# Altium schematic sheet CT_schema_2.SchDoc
size 276 x 169 mm
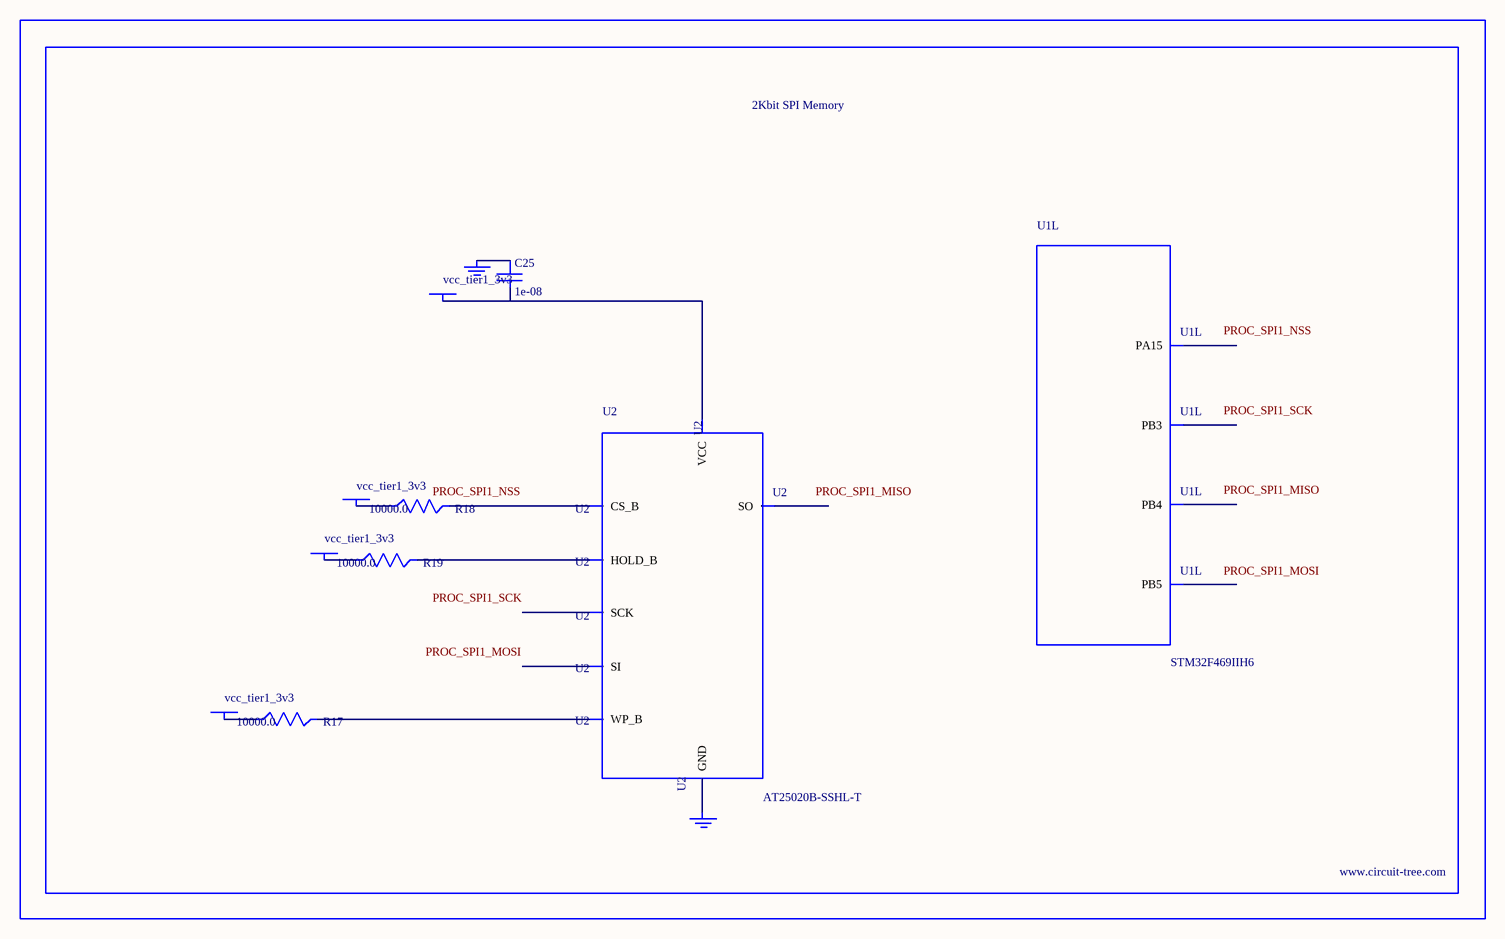
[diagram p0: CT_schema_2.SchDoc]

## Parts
BORDER1  (no value)
C25  1e-08  [C0402]
GND_INSTANCE_1_0  (no value)
GND_INSTANCE_1_1  (no value)
POWER_INSTANCE_1_0  vcc_tier1_3v3
POWER_INSTANCE_1_1  vcc_tier1_3v3
POWER_INSTANCE_1_2  vcc_tier1_3v3
POWER_INSTANCE_1_3  vcc_tier1_3v3
R17  10000.0  [R0603]
R18  10000.0  [R0603]
R19  10000.0  [R0603]
U1  STM32F469IIH6  [UFBGA176]  (part L of 17)
U2  AT25020B-SSHL-T  [SOIC-8]

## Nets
NetC25_1: C25.1 GND_INSTANCE_1_0.0(GND)
NetC25_2: C25.2 POWER_INSTANCE_1_3.0(PWR) U2.8(VCC)
NetGND_INSTANCE_1_1_0: GND_INSTANCE_1_1.0(GND) U2.4(GND)
NetPOWER_INSTANCE_1_0_0: POWER_INSTANCE_1_0.0(PWR) R18.1
NetPOWER_INSTANCE_1_1_0: POWER_INSTANCE_1_1.0(PWR) R17.1
NetPOWER_INSTANCE_1_2_0: POWER_INSTANCE_1_2.0(PWR) R19.1
NetR17_2: R17.2 U2.3(WP_B)
NetR18_2: R18.2 U2.1(CS_B)
NetR19_2: R19.2 U2.7(HOLD_B)

Not connected (* = marked no-connect by the designer): U1 A6(PB5) A9(PB4) A10(PB3) A13(PA15); U2 2(SO) 5(SI) 6(SCK)

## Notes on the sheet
- Labels drawn without touching a wire or pin: PROC_SPI1_MISO, PROC_SPI1_MOSI, PROC_SPI1_NSS, PROC_SPI1_SCK

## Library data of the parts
BORDER1 = BORDER_PAGE1
C25 = C0402C103K3RAC
GND_INSTANCE_1_0 GND_INSTANCE_1_1 = GND
POWER_INSTANCE_1_0-POWER_INSTANCE_1_3 = PWR
R17-R19 = RC0603JR-0710KL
